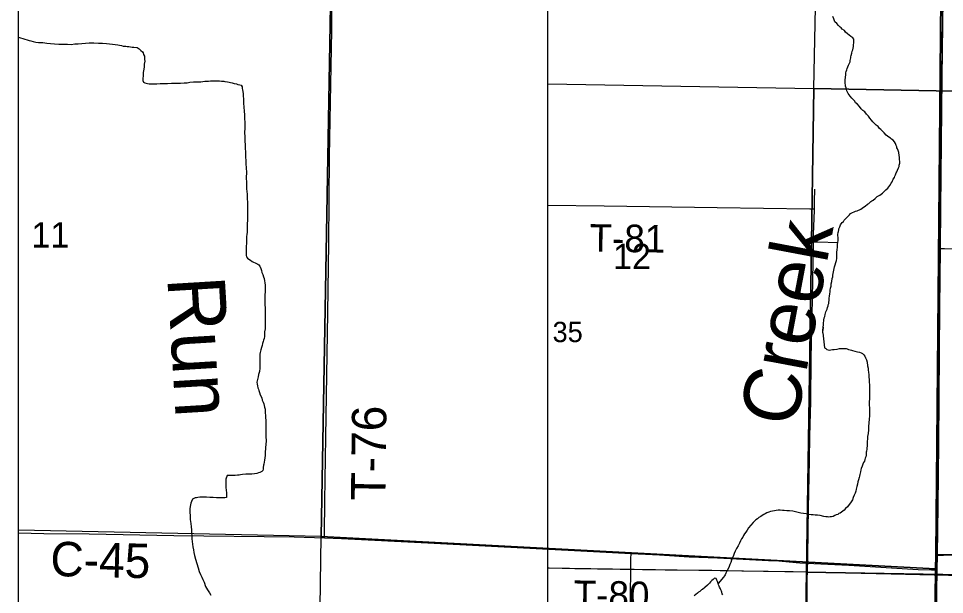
# Model space of a CAD drawing. Extents: x 0 to 68, y 0 to 52.9.
# Drawn here: x 41.105 to 43.122, y 35.26 to 36.513 of the extents above; entities that cross this region are included whole.
import ezdxf

# ---------------------------------------------------------------- set-up
doc = ezdxf.new("R2010")
doc.units = 0
for name, color, linetype in [('Default', 7, 'Continuous'), ('GM_X_County_Road', 7, 'Continuous'), ('GM_X_County_Road_Text', 7, 'Continuous'), ('GM_X_Minor_River', 7, 'Continuous'), ('GM_X_Minor_River_Text', 7, 'Continuous'), ('GM_X_Township', 7, 'Continuous'), ('GM_X_Township_Road', 7, 'Continuous'), ('GM_X_Township_Road_Text', 7, 'Continuous')]:
    doc.layers.add(name, color=color, linetype=linetype)

msp = doc.modelspace()

# ---------------------------------------------------------------- linework, layer by layer
at = {"layer": 'Default'}
for p, q in [((41.1051, 32.7683), (41.1051, 42.0083)), ((42.2581, 31.1431), (42.2581, 38.5351))]:
    msp.add_line(p, q, dxfattribs=at)
for points in [[(43.9204, 37.4103), (43.9206, 37.3983), (43.9027, 36.3407), (42.8372, 36.3611), (42.8588, 37.4239)], [(41.7877, 36.7071), (43.1145, 36.6402), (43.1026, 35.3466), (43.1022, 35.3161), (41.7644, 35.3862)], [(43.1156, 36.6787), (44.3441, 36.6667), (44.3202, 35.3382), (43.6933, 35.3509), (43.1026, 35.3466), (43.1145, 36.6402)], [(42.8372, 36.3611), (43.9027, 36.3407), (43.8802, 35.2907), (42.821, 35.3089)], [(41.7644, 35.3862), (43.1022, 35.3161), (43.0873, 34.0306), (43.0864, 33.9961), (41.7454, 34.0552)], [(43.1026, 35.3466), (43.6933, 35.3509), (44.3202, 35.3382), (44.3032, 34.0046), (43.0873, 34.0306), (43.1022, 35.3161)], [(42.821, 35.3089), (43.8802, 35.2907), (43.8665, 34.2714), (43.8657, 34.2406), (42.8041, 34.2941)]]:
    msp.add_lwpolyline(points, close=True, dxfattribs=at)
for points in [[(43.089, 34.0291), (43.0906, 34.1657), (43.0925, 34.3503), (43.0942, 34.5226), (43.0956, 34.6532), (43.096, 34.6875), (43.0962, 34.7071), (43.0981, 34.8056), (43.1022, 35.0517), (43.1053, 35.2649), (43.1059, 35.3134), (43.1062, 35.3458), (43.1075, 35.4536), (43.1091, 35.5889), (43.1114, 35.8842), (43.1128, 36.0132), (43.1137, 36.1016), (43.1169, 36.3846), (43.1196, 36.6143), (43.12, 36.643), (43.1213, 36.7456), (43.1227, 36.8522)], [(41.1051, 36.7213), (41.7877, 36.7071), (41.7644, 35.3862), (41.1051, 35.4001)], [(42.2581, 36.3712), (42.8372, 36.3611), (42.821, 35.3089), (42.2581, 35.3174)]]:
    msp.add_lwpolyline(points, dxfattribs=at)
at = {"layer": 'GM_X_County_Road'}
for points in [[(41.1051, 35.394), (41.1601, 35.3928), (41.2586, 35.3918), (41.4432, 35.3886), (41.7057, 35.3853), (41.7717, 35.3833)], [(41.7717, 35.3833), (41.8082, 35.3821), (41.9967, 35.3723), (42.3573, 35.3536), (42.4396, 35.3493)], [(42.4198, 34.6871), (42.4225, 34.6909), (42.426, 34.6983), (42.4289, 34.7082), (42.4308, 34.7233), (42.4322, 34.7643), (42.4349, 34.9736), (42.4349, 34.9899), (42.4376, 35.2473), (42.4382, 35.3252), (42.4389, 35.3376), (42.4396, 35.3493)], [(42.4396, 35.3493), (42.5007, 35.3461), (42.5659, 35.3419), (42.5864, 35.3412), (42.627, 35.3401), (42.7386, 35.334), (42.7528, 35.3337), (42.8065, 35.3291), (42.9131, 35.3237), (43.0646, 35.3147), (43.0934, 35.3138), (43.1059, 35.3134)]]:
    msp.add_lwpolyline(points, dxfattribs=at)
at = {"layer": 'GM_X_Minor_River'}
for points in [[(43.0212, 36.1882), (43.0227, 36.1912), (43.0232, 36.1942), (43.0243, 36.1987), (43.0243, 36.2027), (43.0239, 36.2057), (43.0234, 36.2083), (43.0234, 36.2118), (43.0229, 36.2153), (43.022, 36.2218), (43.021, 36.2259), (43.0196, 36.2294), (43.0181, 36.2319), (43.0176, 36.2344), (43.0166, 36.237), (43.0152, 36.2415), (43.0127, 36.245), (43.0097, 36.2486), (43.0062, 36.2511), (43.0037, 36.2532), (43.0007, 36.2552), (42.9977, 36.2573), (42.9947, 36.2593), (42.9903, 36.2649), (42.9858, 36.2689), (42.9828, 36.2715), (42.9803, 36.274), (42.9773, 36.2786), (42.9729, 36.2811), (42.9694, 36.2847), (42.9659, 36.2882), (42.9624, 36.2923), (42.9589, 36.2963), (42.956, 36.3009), (42.952, 36.3055), (42.948, 36.31), (42.944, 36.3131), (42.9405, 36.3171), (42.9366, 36.3222), (42.9311, 36.3273), (42.9281, 36.3298), (42.9261, 36.3333), (42.9227, 36.3369), (42.9197, 36.3399), (42.9162, 36.3445), (42.9142, 36.347), (42.9122, 36.3501), (42.9103, 36.3531), (42.9093, 36.3561), (42.9083, 36.3592), (42.9073, 36.3622), (42.9064, 36.3662), (42.9059, 36.3687), (42.9054, 36.3717), (42.9054, 36.3753), (42.9055, 36.3798), (42.9066, 36.3908), (42.9071, 36.3948), (42.9077, 36.3983), (42.9087, 36.4013), (42.9098, 36.4049), (42.9113, 36.4084), (42.9123, 36.4119), (42.9144, 36.4164), (42.9159, 36.4194), (42.9165, 36.4219), (42.917, 36.4249), (42.9175, 36.4274), (42.918, 36.4299), (42.9186, 36.4329), (42.9196, 36.4379), (42.9207, 36.4424), (42.9217, 36.4449), (42.9233, 36.4524), (42.9238, 36.4569), (42.9239, 36.4595), (42.9244, 36.4645), (42.9239, 36.4685), (42.922, 36.471), (42.9175, 36.4741), (42.914, 36.4771), (42.9105, 36.4797), (42.906, 36.4833), (42.904, 36.4873), (42.899, 36.4904), (42.8966, 36.4929), (42.8941, 36.4944), (42.8906, 36.498), (42.8871, 36.5025), (42.8831, 36.5061), (42.8821, 36.5086), (42.8807, 36.5127), (42.8787, 36.5177)], [(41.1051, 36.4726), (41.1187, 36.4683)], [(41.1187, 36.4683), (41.1242, 36.4667), (41.1282, 36.4656), (41.1322, 36.4646), (41.1372, 36.4635), (41.1427, 36.462), (41.1483, 36.4614), (41.1533, 36.4614), (41.1583, 36.4608), (41.1668, 36.4597), (41.1749, 36.4586), (41.1834, 36.458), (41.1929, 36.4574), (41.2025, 36.4573), (41.2115, 36.4572), (41.2196, 36.4571), (41.2276, 36.4581), (41.2352, 36.4585), (41.2427, 36.4589), (41.2512, 36.4593), (41.2588, 36.4603), (41.2693, 36.4601), (41.2789, 36.46), (41.2879, 36.4594), (41.2965, 36.4589), (41.3035, 36.4583), (41.31, 36.4577), (41.3155, 36.4566), (41.3211, 36.4561), (41.3251, 36.455), (41.3296, 36.4545), (41.3326, 36.4534), (41.3361, 36.4529), (41.3391, 36.4529), (41.3416, 36.4523), (41.3451, 36.4523), (41.3486, 36.4518), (41.3527, 36.4512), (41.3562, 36.4512), (41.3632, 36.4501), (41.3677, 36.4471), (41.3717, 36.444), (41.3747, 36.4409), (41.3767, 36.4384), (41.3776, 36.4349), (41.3791, 36.4314), (41.3796, 36.4283), (41.3795, 36.4243), (41.38, 36.4203), (41.3789, 36.4138), (41.3784, 36.4083), (41.3778, 36.4032), (41.3767, 36.3957), (41.3767, 36.3907), (41.3762, 36.3877), (41.3756, 36.3837), (41.3756, 36.3807), (41.3761, 36.3781), (41.3775, 36.3751), (41.38, 36.3736), (41.383, 36.3725), (41.3861, 36.372), (41.3896, 36.3715), (41.3941, 36.3714), (41.4001, 36.3714), (41.4066, 36.3713), (41.4137, 36.3717), (41.4217, 36.3716), (41.4298, 36.3721), (41.4383, 36.3725), (41.4499, 36.3728), (41.4579, 36.3728), (41.4655, 36.3732), (41.472, 36.3736), (41.4785, 36.3746), (41.4861, 36.3755), (41.4941, 36.3754), (41.5022, 36.3758), (41.5107, 36.3767), (41.5187, 36.3771), (41.5233, 36.3776), (41.5293, 36.378), (41.5424, 36.3774), (41.5474, 36.3768), (41.5519, 36.3768), (41.5544, 36.3763), (41.5604, 36.3752), (41.5639, 36.3747), (41.5664, 36.3741), (41.5705, 36.3731), (41.575, 36.372), (41.5795, 36.371), (41.583, 36.3699), (41.587, 36.3689), (41.59, 36.3684), (41.592, 36.3643), (41.5924, 36.3613), (41.5929, 36.3578), (41.5934, 36.3543), (41.5943, 36.3497), (41.5943, 36.3447)], [(41.5943, 36.3447), (41.5947, 36.3382), (41.5951, 36.3291), (41.5956, 36.3201), (41.5965, 36.3115), (41.5969, 36.304), (41.5973, 36.296), (41.5977, 36.2869), (41.5976, 36.2748), (41.5975, 36.2653), (41.5979, 36.2558), (41.5979, 36.2467), (41.5983, 36.2382), (41.5987, 36.2311), (41.5991, 36.2226), (41.5995, 36.2125), (41.5999, 36.204), (41.6004, 36.197), (41.6008, 36.1884), (41.6012, 36.1779), (41.6011, 36.1673), (41.6015, 36.1558), (41.6019, 36.1427), (41.6028, 36.1311), (41.6032, 36.1211), (41.6036, 36.1135), (41.6035, 36.108), (41.6039, 36.0904), (41.6038, 36.0854), (41.6037, 36.0784), (41.6037, 36.0733), (41.6031, 36.0678), (41.6031, 36.0628), (41.603, 36.0578), (41.603, 36.0533), (41.6029, 36.0487), (41.6024, 36.0437), (41.6018, 36.0387), (41.6018, 36.0337), (41.6012, 36.0287), (41.6012, 36.0226), (41.6006, 36.0191), (41.6006, 36.0151), (41.6006, 36.0121), (41.6005, 36.0081), (41.6005, 36.0041), (41.601, 36.0005), (41.6009, 35.998), (41.6019, 35.9945), (41.6034, 35.992), (41.6064, 35.9894), (41.6099, 35.9874), (41.6139, 35.9848), (41.6169, 35.9833), (41.6204, 35.9817), (41.6234, 35.9802), (41.6259, 35.9787), (41.6284, 35.9776), (41.6309, 35.9746), (41.6328, 35.9691), (41.6343, 35.965), (41.6352, 35.961), (41.6372, 35.9565), (41.6387, 35.9514), (41.6401, 35.9474), (41.6411, 35.9429), (41.6416, 35.9383), (41.6425, 35.9333), (41.6425, 35.9273), (41.6424, 35.9197), (41.6418, 35.9112), (41.6417, 35.9012), (41.6416, 35.8946), (41.642, 35.8795), (41.6424, 35.8755), (41.6424, 35.8715), (41.6424, 35.8665), (41.6423, 35.862), (41.6423, 35.8559), (41.6422, 35.8489), (41.6421, 35.8384), (41.641, 35.8318), (41.641, 35.8278), (41.6409, 35.8248), (41.6404, 35.8213), (41.6399, 35.8173), (41.6388, 35.8138), (41.6378, 35.8103), (41.6367, 35.8063), (41.6357, 35.8018), (41.6341, 35.7977), (41.6326, 35.7927), (41.631, 35.7867), (41.6305, 35.7827), (41.6305, 35.7797), (41.6304, 35.7767), (41.6304, 35.7742), (41.6304, 35.7707), (41.6308, 35.7656), (41.6308, 35.7596), (41.6307, 35.7526)], [(42.8564, 35.8292), (42.8575, 35.8418), (42.8569, 35.8347), (42.8575, 35.8418), (42.8581, 35.8468), (42.8581, 35.8493), (42.8581, 35.8518), (42.8586, 35.8548), (42.8592, 35.8573), (42.8597, 35.8618), (42.8607, 35.8653), (42.8618, 35.8693), (42.8634, 35.8749), (42.8659, 35.8809), (42.867, 35.8844), (42.868, 35.8879), (42.8685, 35.8904), (42.8696, 35.8929), (42.8701, 35.8964), (42.8706, 35.8994), (42.8707, 35.9019), (42.8707, 35.9049), (42.8712, 35.9089), (42.8718, 35.9145), (42.8723, 35.9185), (42.8729, 35.9225), (42.8734, 35.9265), (42.8745, 35.931), (42.875, 35.936), (42.8761, 35.941), (42.8771, 35.9476), (42.8782, 35.9516), (42.8787, 35.9546), (42.8792, 35.9586), (42.8824, 35.9731), (42.8835, 35.9771), (42.885, 35.9821), (42.8861, 35.9871), (42.8871, 35.9912), (42.8871, 35.9937), (42.8872, 35.9962), (42.8872, 36.0002), (42.8872, 36.0042), (42.8878, 36.0107), (42.8883, 36.0148), (42.8889, 36.0183), (42.8889, 36.0208), (42.8889, 36.0233), (42.8895, 36.0263), (42.89, 36.0303), (42.89, 36.0333), (42.8901, 36.0368), (42.8896, 36.0409), (42.8896, 36.0434), (42.8902, 36.0474), (42.8907, 36.0499), (42.8912, 36.0534), (42.8918, 36.0559), (42.8938, 36.0604), (42.8954, 36.0644), (42.8969, 36.0669), (42.8989, 36.0694), (42.9015, 36.0719), (42.9035, 36.0749), (42.9065, 36.0779), (42.9101, 36.0818), (42.9147, 36.0858), (42.9172, 36.0888), (42.9212, 36.0913), (42.9248, 36.0927), (42.9278, 36.0942), (42.9318, 36.0952), (42.9394, 36.0986), (42.9455, 36.1031), (42.949, 36.105), (42.9536, 36.109), (42.9566, 36.111), (42.9612, 36.115), (42.9637, 36.1169), (42.9662, 36.1184), (42.9703, 36.1219), (42.9728, 36.1239), (42.9753, 36.1259), (42.9809, 36.1293), (42.9839, 36.1313), (42.9865, 36.1333), (42.9915, 36.1383), (42.9941, 36.1402), (42.9981, 36.1442), (43.0007, 36.1472), (43.0027, 36.1502), (43.0053, 36.1547), (43.0078, 36.1582), (43.0099, 36.1637), (43.0124, 36.1672), (43.0135, 36.1702), (43.015, 36.1732), (43.0165, 36.1772), (43.0181, 36.1797), (43.0196, 36.1832), (43.0212, 36.1882)], [(42.8564, 35.8292), (42.8606, 35.797), (42.8631, 35.795), (42.8656, 35.7935), (42.8686, 35.7924), (42.8711, 35.7919), (42.8741, 35.7924), (42.8776, 35.7928), (42.8816, 35.7933), (42.8877, 35.7942), (42.8927, 35.7952), (42.8972, 35.7956), (42.9018, 35.7956), (42.9048, 35.7956), (42.9073, 35.795), (42.9098, 35.7945), (42.9128, 35.7935), (42.9163, 35.7924), (42.9188, 35.7919), (42.9213, 35.7909), (42.9263, 35.7898), (42.9293, 35.7888), (42.9323, 35.7882), (42.9363, 35.7872), (42.9404, 35.7856), (42.9434, 35.7841), (42.9458, 35.7816), (42.9478, 35.7785), (42.9498, 35.775), (42.9518, 35.771), (42.9532, 35.7654), (42.9541, 35.7579), (42.9551, 35.7528), (42.9556, 35.7483), (42.956, 35.7438), (42.9565, 35.7378), (42.9569, 35.7327), (42.9574, 35.7277), (42.9578, 35.7222), (42.9583, 35.7166), (42.9582, 35.7096), (42.958, 35.6925), (42.958, 35.686), (42.9579, 35.6795), (42.9578, 35.6729), (42.9583, 35.6654), (42.9582, 35.6574), (42.9581, 35.6488), (42.9575, 35.6413), (42.9569, 35.6333), (42.9564, 35.6257), (42.9558, 35.6187), (42.9552, 35.6107), (42.9541, 35.6042), (42.9536, 35.5981), (42.9535, 35.5936), (42.9535, 35.5896), (42.953, 35.5861), (42.9529, 35.5826), (42.9524, 35.5791), (42.9524, 35.576), (42.9518, 35.572), (42.9513, 35.5695), (42.9513, 35.566), (42.9507, 35.563), (42.9502, 35.5595), (42.9492, 35.5565), (42.9481, 35.5535), (42.9471, 35.5505), (42.9455, 35.547), (42.944, 35.5435), (42.942, 35.539), (42.9404, 35.5345), (42.9394, 35.531), (42.9388, 35.527), (42.9378, 35.524), (42.9373, 35.5209), (42.9362, 35.5179), (42.9357, 35.5144), (42.9346, 35.5099), (42.9331, 35.5049), (42.932, 35.5004), (42.9305, 35.4949), (42.9294, 35.4894), (42.9284, 35.4849), (42.9268, 35.4809), (42.9248, 35.4759), (42.9227, 35.4714), (42.9211, 35.4664), (42.9186, 35.4619), (42.9104, 35.4509), (42.9064, 35.4469), (42.9033, 35.4439), (42.9003, 35.4415), (42.8973, 35.439), (42.8947, 35.437)], [(41.6307, 35.7526), (41.6296, 35.7451), (41.628, 35.7385), (41.627, 35.734), (41.626, 35.731), (41.6254, 35.728), (41.6249, 35.725), (41.6244, 35.722), (41.6248, 35.718), (41.6253, 35.714), (41.6263, 35.7099), (41.6277, 35.7069), (41.6287, 35.7039), (41.6302, 35.6998), (41.6316, 35.6948), (41.6346, 35.6882), (41.636, 35.6832), (41.6375, 35.6782), (41.639, 35.6746), (41.6399, 35.6711), (41.6409, 35.6676), (41.6419, 35.6635), (41.6423, 35.6595), (41.6432, 35.6454), (41.6436, 35.6389), (41.6436, 35.6339), (41.6435, 35.6269), (41.6435, 35.6198), (41.6439, 35.6123), (41.6438, 35.6037), (41.6442, 35.5947), (41.6436, 35.5862), (41.6431, 35.5796), (41.643, 35.5756), (41.6425, 35.5721), (41.6424, 35.5681), (41.6419, 35.5626), (41.6413, 35.5576), (41.6408, 35.5525), (41.6397, 35.548), (41.6392, 35.544), (41.6387, 35.5415), (41.6381, 35.5365), (41.6376, 35.5325), (41.637, 35.53), (41.635, 35.5275), (41.6305, 35.5255), (41.6279, 35.5245), (41.6244, 35.5236), (41.6189, 35.5226), (41.6129, 35.5222), (41.6063, 35.5218), (41.5998, 35.5218), (41.5927, 35.5214), (41.5887, 35.5204), (41.5857, 35.52), (41.5817, 35.5195), (41.5766, 35.5191), (41.5721, 35.5191), (41.5686, 35.5191), (41.5656, 35.5192), (41.5631, 35.5192), (41.5596, 35.5187), (41.5565, 35.5107), (41.5564, 35.5037), (41.5568, 35.4931), (41.5577, 35.4816), (41.5581, 35.474), (41.5581, 35.471), (41.5546, 35.4706), (41.5521, 35.4706), (41.5485, 35.4706), (41.5445, 35.4707), (41.541, 35.4702), (41.5365, 35.4707), (41.5289, 35.4708), (41.5214, 35.4714), (41.5144, 35.4715), (41.5073, 35.4716), (41.4998, 35.4716), (41.4958, 35.4712), (41.4923, 35.4707), (41.4897, 35.4702), (41.4867, 35.4693), (41.4842, 35.4673), (41.4821, 35.4623), (41.4806, 35.4588), (41.4795, 35.4553), (41.479, 35.4513), (41.4785, 35.4462), (41.4784, 35.4382), (41.4788, 35.4317), (41.4792, 35.4231), (41.4802, 35.4146), (41.4811, 35.407), (41.4815, 35.4005), (41.482, 35.394), (41.4824, 35.3874), (41.4828, 35.3814), (41.4847, 35.3638), (41.4861, 35.3572)], [(42.8947, 35.437), (42.8917, 35.436), (42.8892, 35.4345), (42.8856, 35.4331), (42.8826, 35.4321), (42.8791, 35.4301), (42.8756, 35.4292), (42.8725, 35.4287), (42.87, 35.4282), (42.867, 35.4287), (42.8635, 35.4293), (42.859, 35.4298), (42.851, 35.4319), (42.8449, 35.4325), (42.8399, 35.4325), (42.8354, 35.4331), (42.8314, 35.4336), (42.8264, 35.4342), (42.8203, 35.4353), (42.8143, 35.4363), (42.8088, 35.4374), (42.8028, 35.4385), (42.7968, 35.44), (42.7913, 35.4416), (42.7842, 35.4422), (42.7782, 35.4422), (42.7727, 35.4428), (42.7687, 35.4428), (42.7637, 35.4434), (42.7591, 35.4434), (42.7551, 35.4425), (42.7511, 35.442), (42.7471, 35.4415), (42.743, 35.4406), (42.739, 35.4391), (42.7345, 35.4377), (42.7309, 35.4357), (42.7279, 35.4342), (42.7244, 35.4322), (42.7213, 35.4298), (42.7173, 35.4273), (42.7142, 35.4248), (42.7107, 35.4223), (42.7082, 35.4193), (42.7051, 35.4164), (42.6949, 35.4049), (42.6919, 35.4004), (42.6888, 35.3959), (42.6863, 35.3919), (42.6837, 35.3885), (42.6822, 35.385), (42.6796, 35.381), (42.6776, 35.3765), (42.675, 35.3715), (42.672, 35.366), (42.6689, 35.3605), (42.6658, 35.3545), (42.6638, 35.3495), (42.6622, 35.345), (42.6601, 35.3395), (42.6581, 35.335), (42.656, 35.33), (42.6545, 35.3255), (42.6524, 35.321), (42.6504, 35.316), (42.6478, 35.3105), (42.6452, 35.3065), (42.6442, 35.303), (42.6422, 35.3005), (42.6406, 35.298), (42.6284, 35.284)], [(41.4861, 35.3572), (41.4871, 35.3512), (41.4885, 35.3452), (41.4904, 35.3371), (41.4934, 35.3275), (41.4963, 35.318), (41.4987, 35.3104), (41.5017, 35.3038), (41.5041, 35.2978), (41.5061, 35.2927), (41.509, 35.2867), (41.5125, 35.2776), (41.5169, 35.2705), (41.5209, 35.2634), (41.5238, 35.2584)], [(42.6387, 35.2593), (42.6378, 35.2618), (42.6368, 35.2649), (42.6358, 35.2674), (42.6348, 35.2699), (42.6339, 35.2724), (42.6319, 35.276), (42.6309, 35.2785), (42.6294, 35.281), (42.6284, 35.284), (42.627, 35.2881), (42.6255, 35.2916), (42.6245, 35.2951), (42.621, 35.2957), (42.6175, 35.2927), (42.6149, 35.2907), (42.6124, 35.2877), (42.6099, 35.2847), (42.6053, 35.2803), (42.5997, 35.2753), (42.5947, 35.2713), (42.5921, 35.2699), (42.5886, 35.2669), (42.5861, 35.2654), (42.5835, 35.2629), (42.58, 35.2604), (42.5764, 35.2575)]]:
    msp.add_lwpolyline(points, dxfattribs=at)
at = {"layer": 'GM_X_Township'}
msp.add_lwpolyline([(43.0644, 32.7683), (43.0839, 33.9959), (43.0844, 34.0287), (43.0925, 34.6527), (43.0929, 34.6864), (43.1046, 35.3142), (43.1053, 35.3456), (43.1113, 36.0138), (43.1191, 36.6427), (43.1235, 37.0176), (43.1252, 37.2584), (43.1291, 37.4252), (43.1246, 37.4931), (43.125, 37.5147), (43.132, 37.8314), (43.1321, 37.8584), (43.1323, 37.9511), (43.3145, 37.9477), (43.3203, 37.9479), (44.1214, 37.9431), (44.7776, 37.9316), (45.7636, 37.9078)], dxfattribs=at)
at = {"layer": 'GM_X_Township_Road'}
for points in [[(41.7717, 35.3833), (41.7717, 35.3931), (41.7722, 35.4629), (41.7743, 35.6022), (41.7784, 35.8728), (41.7805, 36.0245), (41.7824, 36.2131), (41.7872, 36.4878), (41.7891, 36.66), (41.7899, 36.7061)], [(42.8382, 36.0992), (42.8384, 36.1153), (42.8389, 36.1421)], [(42.2581, 36.1074), (42.3807, 36.1058), (42.6265, 36.1019), (42.8284, 36.0993), (42.8382, 36.0992)], [(42.8364, 36.0275), (42.8367, 36.044), (42.8382, 36.0957), (42.8382, 36.0992)], [(42.8231, 35.3092), (42.8238, 35.339), (42.825, 35.4013), (42.8258, 35.4472), (42.8277, 35.5521), (42.8284, 35.6046), (42.8303, 35.68), (42.8316, 35.7751), (42.8333, 35.8669), (42.8349, 35.9423), (42.8364, 36.0275)], [(42.8364, 36.0275), (42.8457, 36.0273), (42.8903, 36.0263)], [(43.1128, 36.0132), (43.1215, 36.0131), (43.3349, 36.0118), (43.6344, 36.0085), (43.6836, 36.0079), (43.7534, 36.0069), (43.9544, 36.0053), (44.1145, 36.0036), (44.1883, 36.0026), (44.2909, 36.0011), (44.4017, 35.9994), (44.5042, 35.9974), (44.8734, 35.9884), (44.9883, 35.9853), (45.008, 35.9847)], [(43.1062, 35.3458), (43.1156, 35.3456), (43.1197, 35.3455), (43.2469, 35.3466), (43.3905, 35.347), (43.5013, 35.3478), (43.6325, 35.3489), (43.7474, 35.3477), (43.9935, 35.3431), (44.0673, 35.342), (44.2273, 35.339), (44.4652, 35.3342), (44.7811, 35.3281), (44.9961, 35.3218)], [(42.2581, 35.3181), (42.261, 35.3181), (42.3167, 35.317), (42.5136, 35.3136), (42.6153, 35.3127), (42.6842, 35.3113), (42.7924, 35.3098), (42.8231, 35.3092)], [(42.806, 34.2933), (42.8074, 34.3745), (42.8095, 34.4828), (42.8109, 34.5713), (42.8122, 34.6369), (42.8146, 34.827), (42.8197, 35.0729), (42.8212, 35.1681), (42.8222, 35.2566), (42.8229, 35.2959), (42.8231, 35.3092)], [(42.8231, 35.3092), (42.9073, 35.3075), (43.0057, 35.3054), (43.1303, 35.3024), (43.3042, 35.2989), (43.3532, 35.2977)]]:
    msp.add_lwpolyline(points, dxfattribs=at)

# ---------------------------------------------------------------- texts
at = {"layer": 'Default'}
for s, height, p in [('11', 0.05525, (41.1332, 36.0149)), ('12', 0.05525, (42.4001, 35.968)), ('35', 0.0442, (42.2681, 35.8092))]:
    msp.add_text(s, height=height, rotation=0, dxfattribs=at).set_placement(p)
at = {"layer": 'GM_X_County_Road_Text'}
msp.add_text('C-45', height=0.075, rotation=358.6526, dxfattribs=at).set_placement((41.1739, 35.3004))
at = {"layer": 'GM_X_Minor_River_Text'}
for s, rotation, p in [('Creek', 79.3151, (42.7976, 35.6214)), ('Run', 273.4451, (41.429, 35.9492))]:
    msp.add_text(s, height=0.12505, rotation=rotation, dxfattribs=at).set_placement(p)
at = {"layer": 'GM_X_Township_Road_Text'}
for s, height, rotation, p in [('T-81', 0.06, 359.2931, (42.3483, 36.006)), ('T-76', 0.075, 89.2917, (41.9039, 35.4643)), ('T-80', 0.06, 358.9386, (42.3136, 35.2308))]:
    msp.add_text(s, height=height, rotation=rotation, dxfattribs=at).set_placement(p)

doc.saveas('drawing.dxf')
